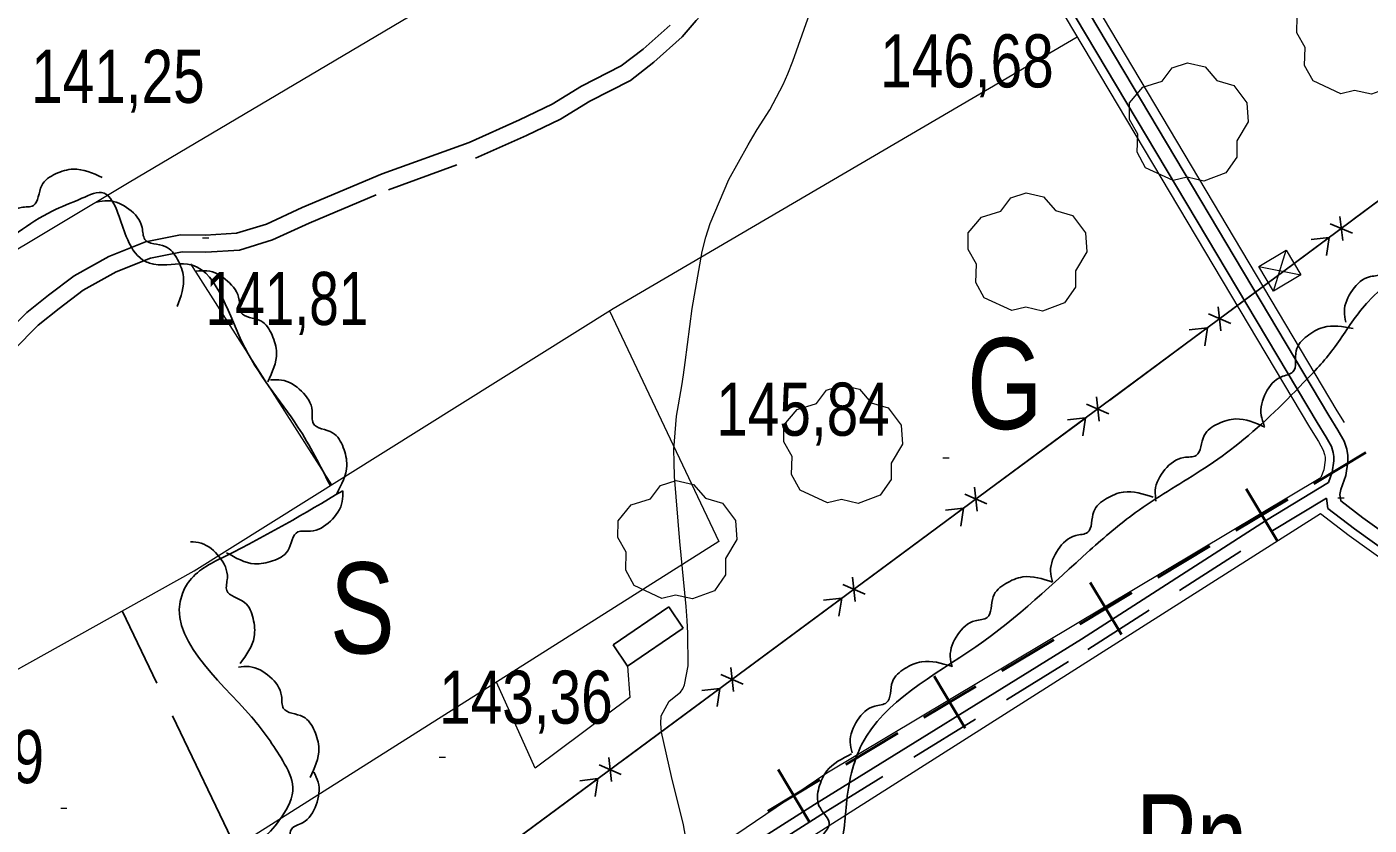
# Model space of a CAD drawing. Extents: x 487425 to 492029, y 4383576 to 4386788.
# Drawn here: x 489846.1 to 490067.5, y 4384214.7 to 4384346.2 of the extents above; entities that cross this region are included whole.
import ezdxf
from ezdxf.enums import TextEntityAlignment as Align

# ---------------------------------------------------------------- set-up
doc = ezdxf.new("R2010")
doc.units = 0
doc.header["$LTSCALE"] = 4
doc.linetypes.add('LONG_DASHED', pattern=[7.5, 6, -1.5])
doc.linetypes.add('MEDIUM_DASHED', pattern=[4.5, 3, -1.5])
for name, color, linetype, lineweight in [('25', 7, 'LONG_DASHED', 25), ('27', 7, 'Continuous', 25), ('29', 7, 'Continuous', 13), ('34', 7, 'Continuous', 35), ('38', 7, 'Continuous', 25), ('43', 7, 'Continuous', 25), ('48', 7, 'MEDIUM_DASHED', 25), ('51', 7, 'Continuous', 13), ('7', 7, 'Continuous', 13), ('9', 7, 'Continuous', 13)]:
    doc.layers.add(name, color=color, linetype=linetype, lineweight=lineweight)
doc.layers.add('31', color=7, linetype='Continuous')

msp = doc.modelspace()

# ---------------------------------------------------------------- linework, layer by layer
at = {"layer": '25'}
msp.add_line((489880.52, 4384211), (489861.85, 4384249.98), dxfattribs=at)
at = {"layer": '27'}
for points in [[(489989.6, 4384125.64), (489987, 4384130.58), (489982.08, 4384141.69), (489979.92, 4384147.02), (489978.16, 4384159.7), (489973.47, 4384169.09), (489980.7, 4384182.48), (489983.34, 4384186.9), (489983.36, 4384192.52), (489982.69, 4384195.75), (489981.43, 4384200.85), (489980.85, 4384204.6), (489980.41, 4384208.8), (489980.34, 4384210.3), (489980.8, 4384213.53), (489981.26, 4384218.17), (489983.84, 4384227.99), (490002.63, 4384244.05), (490021.43, 4384259.97), (490028.94, 4384266.17), (490039.61, 4384273.03), (490045.32, 4384277.06), (490056.68, 4384287.6), (490061.57, 4384293.14), (490066.08, 4384299.5), (490085.32, 4384314.13), (490096.9, 4384322.42), (490101.93, 4384325.03), (490109.67, 4384330.78), (490126.57, 4384341.9), (490133.11, 4384345.63), (490146.03, 4384354.21), (490162.33, 4384364.44), (490168.64, 4384368.62), (490171.71, 4384366.58), (490176.18, 4384357.57), (490180.51, 4384351.56), (490183.05, 4384347.8), (490199.13, 4384360.43), (490221.67, 4384374.38), (490243.98, 4384387.66), (490261.64, 4384401.93), (490277.11, 4384409.9), (490279.44, 4384412.07), (490282.52, 4384414.69), (490294.85, 4384423.42), (490298.3, 4384424.09), (490298.38, 4384425.51), (490297.35, 4384431.81), (490292.61, 4384451.1), (490279.32, 4384495.9), (490282.71, 4384502.19), (490283.1, 4384505.48), (490279.52, 4384511.64), (490273.85, 4384520.43), (490270.19, 4384525.99), (490252.78, 4384545.17), (490249.49, 4384550.95), (490249.73, 4384555.37), (490257.19, 4384566.22), (490273.21, 4384559.72), (490278.37, 4384554.16), (490295.94, 4384536.26), (490300.5, 4384532.5), (490304.24, 4384529.04), (490308.8, 4384524.75), (490314.55, 4384517.39), (490319.7, 4384510.55), (490328.97, 4384499.95), (490336.37, 4384491.68), (490340.93, 4384487.01), (490347.72, 4384477.77)], [(489284.08, 4384302.57), (489286.52, 4384306.29), (489293.79, 4384311.98), (489307.15, 4384319.63), (489316.81, 4384324.7), (489323.74, 4384326.8), (489343.4, 4384333.63), (489350.76, 4384334.14), (489355.18, 4384334.17), (489365.32, 4384334.58), (489385.76, 4384337.72), (489392.97, 4384338.31), (489412.95, 4384340.49), (489421.6, 4384342.49), (489426.79, 4384344.15), (489441.25, 4384349.02), (489443.61, 4384352.14), (489442.1, 4384370.61), (489438.69, 4384380.78), (489441.87, 4384396.35), (489462.11, 4384395.44), (489473.87, 4384387.51), (489487.73, 4384378.95), (489494.89, 4384374.96), (489500.74, 4384368.37), (489500.46, 4384363.42), (489480.02, 4384353.98), (489458.24, 4384344.92), (489445.73, 4384340.71), (489440.76, 4384339.12), (489428.63, 4384334.61), (489428.47, 4384333.48), (489440.65, 4384309.64), (489441.8, 4384304.52), (489447.72, 4384304.31), (489454.75, 4384309.1), (489466.78, 4384317.67), (489471.88, 4384317.61), (489477.04, 4384316.2), (489486.56, 4384309.11), (489490.34, 4384304.87), (489494.13, 4384301.38), (489498.75, 4384299.37), (489502.78, 4384297.53), (489518.56, 4384299.6), (489545.17, 4384310.77), (489553.85, 4384315.33), (489563.04, 4384318.75), (489571.4, 4384321.58), (489574.3, 4384325.9), (489571.66, 4384331.33), (489568.87, 4384336.76), (489567.91, 4384344.42), (489568.56, 4384348.62), (489575.92, 4384355.66), (489585.44, 4384361.71), (489600.21, 4384368.06), (489629.84, 4384380.78), (489662.31, 4384392.87), (489678.29, 4384398.91), (489686.49, 4384400.77), (489691.07, 4384401.62), (489706.79, 4384364.98), (489732.83, 4384326.49), (489754.12, 4384291.82), (489763.77, 4384276.7), (489765.61, 4384273.01), (489768.4, 4384267.72), (489779.65, 4384274.35), (489815.31, 4384296.15), (489839.16, 4384308.4), (489850.27, 4384315.86), (489855.17, 4384317.98), (489858.85, 4384318.83), (489861.14, 4384315.51), (489862.52, 4384311.66), (489865.26, 4384307.81), (489867.05, 4384307.11), (489872.6, 4384307.12), (489881.53, 4384294.42), (489890.83, 4384280.28), (489896.19, 4384270.54)], [(489840.56, 4384309.31), (489840.45, 4384311.08), (489842.06, 4384314.51), (489845.19, 4384316.48), (489847.21, 4384316.8), (489848.57, 4384320.09), (489850.86, 4384322), (489853.78, 4384322.79), (489858.55, 4384321.43)], [(489857.67, 4384317.37), (489859.43, 4384317.59), (489862.96, 4384316.19), (489865.12, 4384313.19), (489865.57, 4384311.19), (489868.93, 4384310.05), (489870.98, 4384307.87), (489871.95, 4384305.01), (489870.9, 4384300.16)], [(490063.64, 4384297.56), (490063.39, 4384299.32), (490064.73, 4384302.86), (490067.69, 4384305.07), (490069.69, 4384305.55), (490070.78, 4384308.93), (490072.92, 4384311.01), (490075.77, 4384312.03), (490080.63, 4384311.05)], [(489874.03, 4384305.95), (489875.81, 4384306.03), (489879.21, 4384304.35), (489881.13, 4384301.2), (489881.42, 4384299.16), (489884.68, 4384297.76), (489886.55, 4384295.43), (489887.29, 4384292.5), (489885.86, 4384287.75)], [(490050.19, 4384280.5), (490049.67, 4384282.2), (490050.44, 4384285.92), (490053.01, 4384288.56), (490054.91, 4384289.35), (490055.45, 4384292.86), (490057.23, 4384295.26), (490059.89, 4384296.71), (490064.84, 4384296.51)], [(489886.32, 4384288.04), (489888.1, 4384288.03), (489891.41, 4384286.18), (489893.17, 4384282.94), (489893.35, 4384280.89), (489896.54, 4384279.32), (489898.29, 4384276.91), (489898.88, 4384273.94), (489897.21, 4384269.27)], [(490032.32, 4384268.06), (490032.21, 4384269.83), (490033.81, 4384273.27), (490036.92, 4384275.26), (490038.94, 4384275.59), (490040.28, 4384278.88), (490042.56, 4384280.81), (490045.48, 4384281.61), (490050.26, 4384280.28)], [(489898.21, 4384269.77), (489878.96, 4384259.04), (489872.98, 4384254.98), (489871.76, 4384252.82), (489883.15, 4384232.51), (489888.32, 4384225.25), (489890, 4384220.88), (489888.14, 4384216.02), (489881.32, 4384209.72), (489864.11, 4384207.29), (489844.77, 4384208.64), (489830.29, 4384208.05), (489821.7, 4384205.07), (489814.43, 4384198.78), (489814.57, 4384192.03), (489816.37, 4384185.1), (489814.35, 4384172.6), (489813.35, 4384170.21), (489803.09, 4384158.62), (489785.16, 4384158.15), (489778.09, 4384157.03), (489763.34, 4384153.07), (489756.06, 4384145.73), (489739.09, 4384131.59), (489731.08, 4384126.28), (489730.65, 4384126.02)], [(489898.21, 4384269.77), (489898.14, 4384268), (489896.17, 4384264.75), (489892.87, 4384263.11), (489890.82, 4384263), (489889.13, 4384259.87), (489886.65, 4384258.21), (489883.67, 4384257.73), (489879.06, 4384259.56)], [(490015.24, 4384254.76), (490014.94, 4384256.51), (490016.19, 4384260.09), (490019.08, 4384262.38), (490021.06, 4384262.92), (490022.06, 4384266.33), (490024.14, 4384268.47), (490026.96, 4384269.56), (490031.84, 4384268.73)], [(489873.09, 4384261.38), (489874.85, 4384261.13), (489877.88, 4384258.85), (489879.18, 4384255.39), (489879.08, 4384253.34), (489882.03, 4384251.35), (489883.43, 4384248.72), (489883.61, 4384245.7), (489881.31, 4384241.3)], [(489998.69, 4384240.72), (489998.39, 4384242.47), (489999.63, 4384246.05), (490002.51, 4384248.35), (490004.49, 4384248.89), (490005.48, 4384252.31), (490007.55, 4384254.46), (490010.37, 4384255.56), (490015.26, 4384254.73)], [(489881.02, 4384240.71), (489882.8, 4384240.79), (489886.2, 4384239.11), (489888.12, 4384235.96), (489888.41, 4384233.92), (489891.67, 4384232.52), (489893.54, 4384230.19), (489894.28, 4384227.26), (489892.85, 4384222.51)], [(489982.23, 4384226.59), (489981.9, 4384228.33), (489983.08, 4384231.93), (489985.94, 4384234.27), (489987.91, 4384234.84), (489988.85, 4384238.27), (489990.89, 4384240.45), (489993.69, 4384241.59), (489998.6, 4384240.83)], [(489979.92, 4384204.79), (489978.49, 4384205.84), (489976.88, 4384209.28), (489977.36, 4384212.94), (489978.42, 4384214.7), (489976.75, 4384217.85), (489976.75, 4384220.83), (489978.02, 4384223.58), (489982.11, 4384226.38)], [(489893.44, 4384223.38), (489894.16, 4384221.76), (489893.83, 4384217.98), (489891.58, 4384215.05), (489889.79, 4384214.05), (489889.66, 4384210.5), (489888.17, 4384207.91), (489885.7, 4384206.16), (489880.76, 4384205.78)]]:
    msp.add_spline(points, degree=3, dxfattribs=at)
at = {"layer": '29'}
for points in [[(490062.79, 4384335.22), (490058.25, 4384337.34), (490056.84, 4384339.88), (490056.94, 4384342.86), (490055.57, 4384345.27), (490055.61, 4384348.02), (490057.77, 4384350.62), (490060.96, 4384351.62), (490062.61, 4384353.81), (490065.18, 4384354.64), (490068.04, 4384353.99), (490069.99, 4384351.72), (490072.8, 4384350.9), (490074.93, 4384348.05), (490075.17, 4384344.92), (490073.29, 4384341.77), (490073.29, 4384339.09), (490071.47, 4384336.48), (490067.85, 4384335.14), (490065.08, 4384335.77)], [(490035.16, 4384320.91), (490030.62, 4384323.03), (490029.21, 4384325.57), (490029.31, 4384328.55), (490027.94, 4384330.96), (490027.98, 4384333.71), (490030.14, 4384336.31), (490033.33, 4384337.31), (490034.98, 4384339.5), (490037.55, 4384340.33), (490040.41, 4384339.68), (490042.36, 4384337.41), (490045.17, 4384336.59), (490047.3, 4384333.74), (490047.54, 4384330.61), (490045.66, 4384327.46), (490045.66, 4384324.78), (490043.84, 4384322.17), (490040.22, 4384320.83), (490037.45, 4384321.46)], [(490008.55, 4384299.47), (490004.01, 4384301.59), (490002.6, 4384304.13), (490002.7, 4384307.11), (490001.33, 4384309.52), (490001.37, 4384312.27), (490003.53, 4384314.87), (490006.72, 4384315.87), (490008.37, 4384318.06), (490010.94, 4384318.89), (490013.8, 4384318.24), (490015.75, 4384315.97), (490018.56, 4384315.15), (490020.69, 4384312.3), (490020.93, 4384309.17), (490019.05, 4384306.02), (490019.05, 4384303.34), (490017.23, 4384300.73), (490013.61, 4384299.39), (490010.84, 4384300.02)], [(489978.16, 4384267.77), (489973.62, 4384269.89), (489972.21, 4384272.43), (489972.31, 4384275.41), (489970.94, 4384277.82), (489970.98, 4384280.57), (489973.14, 4384283.17), (489976.33, 4384284.17), (489977.98, 4384286.36), (489980.55, 4384287.19), (489983.41, 4384286.54), (489985.36, 4384284.27), (489988.17, 4384283.45), (489990.3, 4384280.6), (489990.54, 4384277.47), (489988.66, 4384274.32), (489988.66, 4384271.64), (489986.84, 4384269.03), (489983.22, 4384267.69), (489980.45, 4384268.32)], [(489950.82, 4384252.03), (489946.28, 4384254.15), (489944.87, 4384256.69), (489944.97, 4384259.67), (489943.6, 4384262.08), (489943.64, 4384264.83), (489945.8, 4384267.43), (489948.99, 4384268.43), (489950.64, 4384270.62), (489953.21, 4384271.45), (489956.07, 4384270.8), (489958.02, 4384268.53), (489960.83, 4384267.71), (489962.96, 4384264.86), (489963.2, 4384261.73), (489961.32, 4384258.58), (489961.32, 4384255.9), (489959.5, 4384253.29), (489955.88, 4384251.95), (489953.11, 4384252.58)]]:
    msp.add_lwpolyline(points, close=True, dxfattribs=at)
at = {"layer": '34'}
for p, q in [((490066.94, 4384276.06), (490058.36, 4384270.92)), ((490047.21, 4384270.07), (490052.35, 4384261.49)), ((490054.07, 4384268.35), (490045.49, 4384263.21)), ((490041.21, 4384260.64), (490032.63, 4384255.5)), ((490021.48, 4384254.65), (490026.62, 4384246.07)), ((490028.34, 4384252.93), (490019.76, 4384247.79)), ((490015.47, 4384245.22), (490006.89, 4384240.09)), ((489995.74, 4384239.23), (490000.88, 4384230.66)), ((490002.6, 4384237.52), (489994.02, 4384232.38)), ((489989.74, 4384229.81), (489981.16, 4384224.67)), ((489970.01, 4384223.82), (489975.15, 4384215.24)), ((489976.87, 4384222.1), (489968.29, 4384216.96))]:
    msp.add_line(p, q, dxfattribs=at)
at = {"layer": '38'}
for points in [[(490060.79, 4384271.12), (490061.4, 4384272.85), (490061.66, 4384274.72), (490061.67, 4384275.4), (490061.56, 4384276.08), (490061.26, 4384277.05), (490060.38, 4384278.62), (490058.9, 4384281), (489995.99, 4384386.64)], [(490225.63, 4384153.73), (490175.71, 4384188.23), (490124.76, 4384223.63), (490079.57, 4384255.92), (490066.42, 4384265.32), (490062.81, 4384268.11), (490062.66, 4384269.14), (490062.79, 4384269.98), (490063.62, 4384272.3), (490063.94, 4384274.54), (490063.96, 4384275.58), (490063.78, 4384276.61), (490063.37, 4384277.95), (490062.34, 4384279.78), (490060.85, 4384282.19), (490019.98, 4384350.82)], [(489841.74, 4384294.7), (489846.12, 4384299.14), (489849.7, 4384302.02), (489853.9, 4384305.19), (489859.63, 4384308.38), (489865.68, 4384310.81), (489871.47, 4384311.94), (489875.58, 4384311.93), (489880.7, 4384312.22), (489885.65, 4384313.73), (489891.54, 4384316.46), (489904.71, 4384321.99), (489919.04, 4384327.19), (489927.34, 4384330.9), (489932.77, 4384333.48), (489937.57, 4384336.46), (489944.14, 4384339.8), (489947.73, 4384342.56), (489952.18, 4384346.54)], [(489830.86, 4384125.87), (489882.01, 4384158.28), (489927.18, 4384187.53), (489952.34, 4384202.99), (489976, 4384218.05), (490020.03, 4384245.29), (490050.53, 4384264.93), (490060.79, 4384271.12)], [(490115.82, 4384227.22), (490078.24, 4384254.07), (490065.05, 4384263.49), (490060.69, 4384266.87), (490060.43, 4384268.57)]]:
    msp.add_lwpolyline(points, dxfattribs=at)
at = {"layer": '38', "linetype": 'MEDIUM_DASHED'}
for points in [[(489843.94, 4384292.95), (489848, 4384297.06), (489851.42, 4384299.81), (489855.43, 4384302.84), (489860.83, 4384305.85), (489866.48, 4384308.12), (489871.74, 4384309.14), (489875.65, 4384309.13), (489881.19, 4384309.44), (489886.65, 4384311.11), (489892.67, 4384313.9), (489905.73, 4384319.38), (489920.09, 4384324.6), (489928.51, 4384328.35), (489934.11, 4384331.02), (489938.94, 4384334.01), (489945.64, 4384337.42), (489949.52, 4384340.4), (489954.18, 4384344.58), (489956.5, 4384347.27), (489959.54, 4384350.57), (489962.88, 4384352.74), (489967.26, 4384356.31), (489970.38, 4384359.5)], [(489952.14, 4384200.52), (489953.4, 4384201.29), (489977.06, 4384216.36), (490021.09, 4384243.6), (490051.59, 4384263.23), (490060.43, 4384268.57)]]:
    msp.add_lwpolyline(points, dxfattribs=at)
at = {"layer": '43'}
for p, q in [((490064.87, 4384314.49), (490080.92, 4384326.43)), ((490064.73, 4384312.22), (490061.06, 4384313.8)), ((490063.13, 4384311.03), (490062.67, 4384315)), ((490060.89, 4384311.53), (490057.91, 4384311.18)), ((490060.89, 4384311.53), (490060.45, 4384308.56)), ((490043.04, 4384296.14), (490042.59, 4384300.11)), ((490044.65, 4384297.32), (490040.99, 4384298.92)), ((490024.7, 4384284.72), (490040.78, 4384296.62)), ((490040.8, 4384296.64), (490037.82, 4384296.3)), ((490040.8, 4384296.64), (490040.36, 4384293.68)), ((490022.94, 4384281.27), (490022.49, 4384285.24)), ((490024.55, 4384282.46), (490020.88, 4384284.05)), ((490004.6, 4384269.85), (490020.68, 4384281.75)), ((490020.7, 4384281.78), (490017.72, 4384281.44)), ((490020.7, 4384281.78), (490020.26, 4384278.81)), ((490004.45, 4384267.6), (490000.78, 4384269.19)), ((490002.84, 4384266.41), (490002.39, 4384270.38)), ((489984.5, 4384254.98), (490000.58, 4384266.88)), ((490000.6, 4384266.92), (489997.62, 4384266.58)), ((490000.6, 4384266.92), (490000.16, 4384263.95)), ((489984.35, 4384252.73), (489980.68, 4384254.33)), ((489982.74, 4384251.54), (489982.29, 4384255.52)), ((489964.4, 4384240.12), (489980.48, 4384252.01)), ((489980.5, 4384252.05), (489977.52, 4384251.71)), ((489980.5, 4384252.05), (489980.05, 4384249.09)), ((489962.64, 4384236.68), (489962.19, 4384240.65)), ((489964.24, 4384237.87), (489960.58, 4384239.46)), ((489944.3, 4384225.26), (489960.38, 4384237.15)), ((489960.4, 4384237.19), (489957.41, 4384236.85)), ((489960.4, 4384237.19), (489959.95, 4384234.22)), ((489944.14, 4384223.01), (489940.48, 4384224.6)), ((489942.54, 4384221.82), (489942.09, 4384225.79)), ((489924.2, 4384210.4), (489940.28, 4384222.29)), ((489940.29, 4384222.32), (489937.31, 4384221.98)), ((489940.29, 4384222.32), (489939.85, 4384219.36))]:
    msp.add_line(p, q, dxfattribs=at)
at = {"layer": '43', "lineweight": 13}
for p, q in [((490051.7, 4384302.7), (490053.8, 4384309.41)), ((490049.3, 4384306.73), (490056.2, 4384305.38))]:
    msp.add_line(p, q, dxfattribs=at)
at = {"layer": '43'}
for points in [[(489809.89, 4384125.9), (490053.43, 4384305.98), (490295.56, 4384486.1), (490534.15, 4384662.33), (490743.89, 4384815.26), (490986.91, 4384995.23), (491244.37, 4385186.39)], [(490044.8, 4384299.59), (490053.43, 4384305.98), (490060.86, 4384311.51)]]:
    msp.add_lwpolyline(points, dxfattribs=at)
at = {"layer": '43', "lineweight": 13}
msp.add_lwpolyline([(490051.7, 4384302.7), (490049.3, 4384306.73), (490053.8, 4384309.41), (490056.2, 4384305.38)], close=True, dxfattribs=at)
at = {"layer": '48'}
msp.add_lwpolyline([(489951.97, 4384250.65), (489942.79, 4384244.36), (489945.19, 4384240.85), (489954.37, 4384247.14)], close=True, dxfattribs=at)
at = {"layer": '51'}
for p, q in [((489873.11, 4384307.2), (489896.35, 4384270.74)), ((490059.48, 4384265.98), (489957.07, 4384201))]:
    msp.add_line(p, q, dxfattribs=at)
for points in [[(489768.12, 4384266.39), (489780.82, 4384271.48), (489863, 4384320.66), (489948.5, 4384371.3), (489987.2, 4384396.45)], [(489998.66, 4384379.33), (490057.66, 4384280.24), (490059.13, 4384277.88), (490059.92, 4384276.47), (490060.14, 4384275.75), (490060.21, 4384275.29), (490060.21, 4384274.83), (490059.98, 4384273.2), (490059.53, 4384271.96)], [(490023.6, 4384347.71), (490062.14, 4384282.97), (490063.34, 4384281.04)], [(489798.42, 4384214.9), (489832.77, 4384233.77), (489873.71, 4384256.59), (489942.82, 4384299.79), (490019.34, 4384344.6)], [(489942.21, 4384299.41), (489960.25, 4384261.43), (489872.58, 4384205.98), (489891.51, 4384167.68), (489845.3, 4384137.31)], [(489891.16, 4384167.45), (489944.62, 4384200.66), (489978.05, 4384223.28), (490059.53, 4384271.96)], [(490113.73, 4384226.91), (490077.39, 4384252.89), (490064.18, 4384262.32), (490059.48, 4384265.98)], [(489945.19, 4384240.85), (489945.55, 4384235.68), (489929.92, 4384224.03), (489923.57, 4384238.23)]]:
    msp.add_lwpolyline(points, dxfattribs=at)
at = {"layer": '7'}
for p, q in [((489875.1, 4384311.47), (489876.1, 4384311.47)), ((489997.2, 4384275.18), (489998.2, 4384275.18)), ((490062.34, 4384268.61), (490063.34, 4384268.61)), ((489914.13, 4384225.87), (489915.13, 4384225.87)), ((489851.72, 4384217.44), (489852.72, 4384217.44))]:
    msp.add_line(p, q, dxfattribs=at)
at = {"layer": '9'}
for points in [[(489952.81, 4384276.6), (489953.23, 4384282.06), (489954.13, 4384287.08), (489954.41, 4384288.9), (489954.69, 4384290.92), (489955.82, 4384299.79), (489957.47, 4384309.2), (489958.09, 4384311.56), (489958.79, 4384313.82), (489961.87, 4384321.07), (489965.07, 4384326.82), (489965.84, 4384328.12), (489966.55, 4384329.31), (489968.67, 4384332.55), (489970.85, 4384336.74), (489971.6, 4384338.52), (489972.41, 4384340.57), (489975.83, 4384350.21)], [(489954.73, 4384212.83), (489954.38, 4384214.71), (489952.4, 4384222.67), (489950.8, 4384229.96), (489950.69, 4384231.43), (489950.72, 4384232.66), (489952.04, 4384235.11), (489953.89, 4384236.55), (489954.27, 4384237.13), (489954.58, 4384237.8), (489955.2, 4384240.92), (489955.12, 4384246.28), (489955, 4384248.37), (489954.82, 4384250.72), (489953.82, 4384261.41), (489952.94, 4384272.12), (489952.84, 4384274.49), (489952.81, 4384276.6)]]:
    msp.add_lwpolyline(points, dxfattribs=at)

# ---------------------------------------------------------------- texts
at = {"layer": '31'}
for s, width, p in [('G', 0.8, (490007.41, 4384279.95)), ('S', 0.8, (489901.43, 4384242.96)), ('Pn', 0.75, (490038.22, 4384204.74))]:
    msp.add_text(s, height=15, dxfattribs=dict(at, width=width)).set_placement(p, align=Align.CENTER)
at = {"layer": '7'}
for s, width, p in [('146,68', 0.8, (489986.83, 4384336.26)), ('141,25', 0.8, (489846.81, 4384333.71)), ('141,81', 0.75, (489875.6, 4384297.1)), ('145,84', 0.8, (489959.8, 4384278.85)), ('143,36', 0.8, (489914.1, 4384231.38)), ('143,99', 0.8, (489820.33, 4384221.57))]:
    msp.add_text(s, height=8.75, dxfattribs=dict(at, width=width)).set_placement(p)

doc.saveas('drawing.dxf')
